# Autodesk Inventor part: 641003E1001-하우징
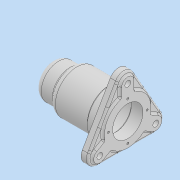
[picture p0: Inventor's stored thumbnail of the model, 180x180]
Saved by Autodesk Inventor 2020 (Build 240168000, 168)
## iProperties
Created: 2024-10
Part Number: 641003E1001-하우징
Material: 하우징
Document SubType Name: Modeling
Designer: oem
Density: 7.85 g/cm^3
Appearance: 기본값
Author: oem
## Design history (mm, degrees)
sketch "스케치1"
  geometry: C1 r 27 at (0, 0); 1 further point
  constraints: 1 centre point, 1 coincident
  dimensions: "d0" = 54 diameter of C1
extrude "돌출1" new body sketch "스케치1" distance "d1" = 29; taper "d2" = 0 deg
sketch "스케치2"
  geometry: C1 r 27 at (0, 0) reference; C2 r 33.5 at (0, 0)
  constraints: 1 centre point, 1 coincident
  dimensions: "d3" = 67 diameter of C2
extrude "돌출2" join sketch "스케치2" distance "d4" = 62; taper "d5" = 0 deg
sketch "스케치3"
  geometry: C1 r 33.5 at (0, 0) reference; C2 r 36.5 at (0, 0)
  constraints: 1 centre point, 1 coincident
  dimensions: "d6" = 73 diameter of C2
extrude "돌출3" join sketch "스케치3" distance "d7" = 12; taper "d8" = 0 deg
sketch "스케치4" dims "d9" = 100
  geometry: L1 (-12.99, 57.5)-(-56.292, -17.5); L2 (12.99, 57.5)-(56.292, -17.5); L3 (-43.301, -40)-(43.301, -40); C1 r 36.5 at (0, 0) reference; A1 r 15 centre (0, 50) between (-12.99, 57.5) and (12.99, 57.5); A2 r 15 centre (-43.301, -25) between (-43.301, -40) and (-56.292, -17.5); A3 r 15 centre (43.301, -25) between (43.301, -40) and (56.292, -17.5); 1 further point
  constraints: 6 end point, 6 point on circle, 5 tangent, 3 centre point, 2 vertical alignment, 1 coincident, 1 horizontal, 9 other
  dimensions: "d10" = 30 diameter of A1; "d13" = 360 deg dimension on C1.centre A1.centre (derived)
extrude "돌출4" join sketch "스케치4" distance "d15" = 11; taper "d16" = 0 deg
sketch "스케치5"
  geometry: L1 (-9.5, 50)-(-9.5, 34.724); L2 (9.5, 50)-(9.5, 34.724); L3 (-38.551, -33.227)-(-25.322, -25.589); L4 (-48.051, -16.773)-(-34.822, -9.135); L5 (48.051, -16.773)-(34.822, -9.135); L6 (38.551, -33.227)-(25.322, -25.589); A1 r 15 centre (0, 50) between (12.99, 57.5) and (-12.99, 57.5) reference; A2 r 9.5 centre (0, 50) between (9.5, 50) and (-9.5, 50); A3 r 9.5 centre (-43.301, -25) between (-48.051, -16.773) and (-38.551, -33.227); A4 r 9.5 centre (43.301, -25) between (38.551, -33.227) and (48.051, -16.773); A5 r 36 centre (0, 0) between (-9.5, 34.724) and (-34.822, -9.135); A6 r 36 centre (0, 0) between (-25.322, -25.589) and (25.322, -25.589); A7 r 36 centre (0, 0) between (34.822, -9.135) and (9.5, 34.724); 1 further point
  constraints: 12 end point, 12 point on circle, 6 centre point, 2 tangent, 2 vertical, 1 coincident, 1 concentric, 25 other
  dimensions: "d17" = 19 diameter of A2; "d21" = 360 deg dimension on point (0, 0) A2.centre (derived); "d23" = 36 radius of A7
extrude "돌출5" join sketch "스케치5" distance "d24" = 3; taper "d25" = 0 deg
sketch "스케치6"
  geometry: A1 r 9.5 centre (0, 50) between (9.5, 50) and (-9.5, 50) reference; A2 r 9.5 centre (-43.301, -25) between (-48.051, -16.773) and (-38.551, -33.227) reference; A3 r 9.5 centre (43.301, -25) between (38.551, -33.227) and (48.051, -16.773) reference
hole "구멍1" sketch "스케치6" at (0, 50), (43.301, -25), (-43.301, -25) diameter "d26" = 9; stored, may be unused: countersink angle "d30" = 90 deg, drill point angle "d32" = 118 deg; dims "d27" = 8, "d28" = 4, "d29" = 2, "d31" = 8
sketch "스케치7"
  geometry: C1 r 23.5 at (0, 0); A1 r 36 centre (0, 0) between (-25.322, -25.589) and (25.322, -25.589) reference
  constraints: 1 centre point, 1 coincident
  dimensions: "d33" = 47 diameter of C1
extrude "돌출6" cut sketch "스케치7" distance "d34" = 18; taper "d35" = 0 deg
sketch "스케치8"
  geometry: C1 r 23.5 at (0, 0) reference; C2 r 26.5 at (0, 0)
  constraints: 1 centre point, 1 coincident
  dimensions: "d36" = 53 diameter of C2
extrude "돌출7" cut sketch "스케치8" distance "d37" = 48; taper "d38" = 0 deg
sketch "스케치9"
  geometry: C1 r 26.5 at (0, 0) reference; C2 r 23.5 at (0, 0)
  constraints: 1 centre point, 1 coincident
  dimensions: "d39" = 47 diameter of C2
extrude "돌출8" cut sketch "스케치9" distance "d40" = 14; taper "d41" = 0 deg
sketch "스케치10"
  geometry: C1 r 23.5 at (0, 0) reference; C2 r 21 at (0, 0)
  constraints: 1 centre point, 1 coincident
  dimensions: "d42" = 42 diameter of C2
extrude "돌출9" cut sketch "스케치10" distance "d43" = 18; taper "d44" = 0 deg
sketch "스케치11"
  geometry: C1 r 21 at (0, 0) reference; C2 r 17.5 at (0, 0)
  constraints: 1 centre point, 1 coincident
  dimensions: "d45" = 35 diameter of C2
extrude "돌출10" cut sketch "스케치11" distance "d46" = 4; taper "d47" = 0 deg
sketch "스케치12"
  geometry: C1 r 17.5 at (0, 0) reference; C2 r 12 at (0, 0)
  constraints: 1 centre point, 1 coincident
  dimensions: "d48" = 24 diameter of C2
extrude "돌출11" cut sketch "스케치12" distance "d49" = 5; taper "d50" = 0 deg
fillet "모깎기1" dims "d54" = 3
fillet "모깎기2" dims "d55" = 1
fillet "모깎기3" dims "d56" = 3
fillet "모깎기4" dims "d57" = 1
fillet "모깎기5" dims "d58" = 10
fillet "모깎기6" dims "d59" = 3
fillet "모깎기7" dims "d60" = 3
fillet "모깎기8" dims "d61" = 3
fillet "모깎기9" dims "d62" = 3
sketch "스케치13"
  geometry: C1 r 23.5 at (0, 0) reference; 1 further point
  constraints: 1 vertical alignment
  dimensions: "d63" = 30 distance of C1.centre point (0, 30)
hole "구멍2" sketch "스케치13" at (0, 30) diameter "d64" = 3.242; stored, may be unused: countersink angle "d68" = 90 deg, drill point angle "d70" = 118 deg; dims "d65" = 10, "d66" = 4, "d67" = 2, "d69" = 12
node "솔리드1"
pattern_circular "원형 패턴1" dims angle "d72" = 360 deg
feature "A9D066F2-1C7D-4E18-AEED-F7BC21143FA4" dims "d26" = 9, "d27" = 8, "d28" = 4, "d29" = 2, "d30" = 90 deg, "d31" = 8, "d32" = 118 deg
other parameters: "d18" = 72
